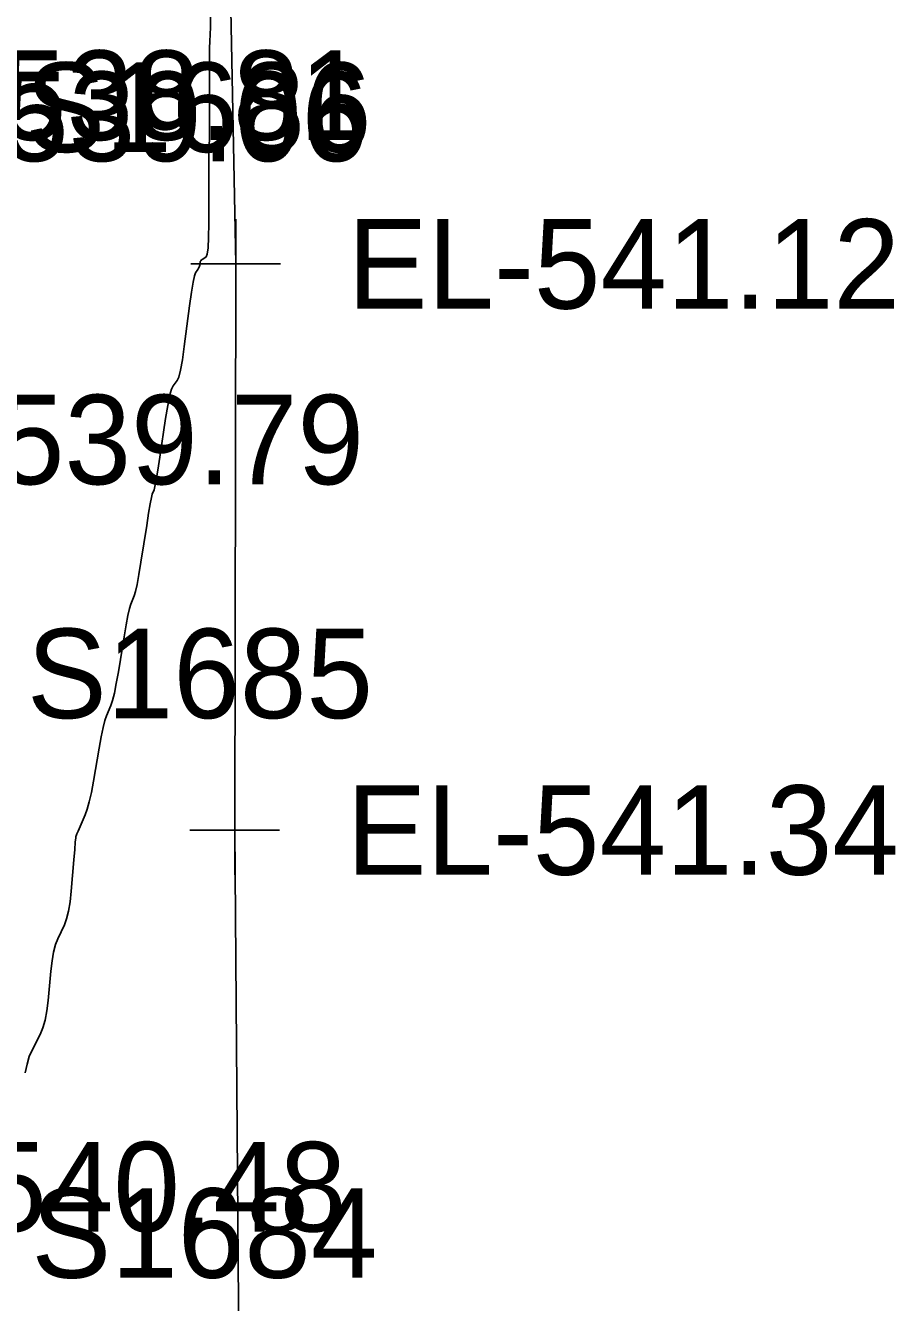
# Model space of a CAD drawing. Extents: x 1724534 to 1727318, y 657156 to 660047.
# Drawn here: x 1725539.2 to 1725578.1, y 658943.2 to 659000.3 of the extents above; entities that cross this region are included whole.
import ezdxf

# ---------------------------------------------------------------- set-up
doc = ezdxf.new("R2010")
doc.units = 0
for name, color, linetype in [('SURVEY - CONTOURS - Intermediate with optional Text', 7, 'Continuous'), ('SURVEY - DTM - Breaklines - Points - Elevations', 7, 'Continuous'), ('SURVEY - TRANSPORTATION - Features', 7, 'Continuous'), ('SURVEY - TRANSPORTATION - Features - Points - Elevations', 7, 'Continuous'), ('SURVEY - TRANSPORTATION - Features - Points - Locators', 7, 'Continuous'), ('SURVEY - TRANSPORTATION - Features - Points - Numbers', 7, 'Continuous')]:
    doc.layers.add(name, color=color, linetype=linetype)

msp = doc.modelspace()

# ---------------------------------------------------------------- linework, layer by layer
at = {"layer": 'SURVEY - CONTOURS - Intermediate with optional Text'}
msp.add_lwpolyline([(1725539.175, 658953.469), (1725539.254, 658953.853), (1725539.356, 658954.189), (1725539.48, 658954.478), (1725539.841, 658955.183), (1725539.965, 658955.477), (1725540.066, 658955.826), (1725540.145, 658956.233), (1725540.201, 658956.697), (1725540.319, 658958.009), (1725540.372, 658958.468), (1725540.441, 658958.863), (1725540.527, 658959.193), (1725540.629, 658959.458), (1725540.922, 658960.078), (1725541.024, 658960.346), (1725541.109, 658960.688), (1725541.178, 658961.102), (1725541.229, 658961.589), (1725541.345, 658962.984), (1725541.383, 658963.442), (1725541.411, 658963.769), (1725541.427, 658963.966), (1725541.433, 658964.036), (1725541.444, 658964.063), (1725541.478, 658964.14), (1725541.534, 658964.268), (1725541.854, 658964.993), (1725541.944, 658965.241), (1725542.036, 658965.576), (1725542.129, 658965.998), (1725542.223, 658966.507), (1725542.477, 658967.979), (1725542.568, 658968.484), (1725542.655, 658968.893), (1725542.735, 658969.207), (1725542.809, 658969.425), (1725543, 658969.88), (1725543.074, 658970.103), (1725543.155, 658970.429), (1725543.242, 658970.859), (1725543.334, 658971.393), (1725543.589, 658972.955), (1725543.68, 658973.485), (1725543.761, 658973.903), (1725543.832, 658974.21), (1725543.892, 658974.405), (1725544.041, 658974.777), (1725544.102, 658974.976), (1725544.173, 658975.294), (1725544.254, 658975.732), (1725544.344, 658976.289), (1725544.6, 658977.932), (1725544.688, 658978.481), (1725544.759, 658978.895), (1725544.813, 658979.175), (1725544.851, 658979.319), (1725544.93, 658979.526), (1725544.968, 658979.674), (1725545.023, 658979.966), (1725545.096, 658980.4), (1725545.185, 658980.977), (1725545.445, 658982.706), (1725545.54, 658983.284), (1725545.627, 658983.721), (1725545.707, 658984.017), (1725545.779, 658984.172), (1725545.964, 658984.398), (1725546.035, 658984.557), (1725546.112, 658984.866), (1725546.194, 658985.324), (1725546.281, 658985.931), (1725546.519, 658987.749), (1725546.602, 658988.353), (1725546.673, 658988.8), (1725546.731, 658989.09), (1725546.777, 658989.223), (1725546.882, 658989.37), (1725546.917, 658989.423), (1725546.944, 658989.473), (1725546.962, 658989.52), (1725546.971, 658989.564), (1725546.984, 658989.675), (1725546.995, 658989.717), (1725547.019, 658989.756), (1725547.056, 658989.795), (1725547.107, 658989.831), (1725547.257, 658989.927), (1725547.307, 658990.047), (1725547.343, 658990.335), (1725547.364, 658990.791), (1725547.372, 658991.415), (1725547.375, 658993.924), (1725547.378, 658994.374), (1725547.381, 658994.653), (1725547.385, 658994.761), (1725547.396, 658994.82), (1725547.4, 658994.928), (1725547.403, 658995.209), (1725547.405, 658995.663), (1725547.406, 658996.289), (1725547.407, 658998.189), (1725547.408, 658998.817), (1725547.411, 658999.274), (1725547.415, 658999.562), (1725547.421, 658999.681), (1725547.438, 658999.77), (1725547.444, 658999.888), (1725547.448, 659000.178), (1725547.45, 659000.638)], dxfattribs=at)
at = {"layer": 'SURVEY - TRANSPORTATION - Features'}
msp.add_lwpolyline([(1725552.257, 658864.379), (1725550.906, 658889.348), (1725550.236, 658914.341), (1725548.733, 658939.305), (1725548.535, 658964.315), (1725548.579, 658989.617), (1725548.091, 659014.622), (1725548.852, 659039.619), (1725549.567, 659064.874), (1725549.301, 659089.91), (1725550.369, 659114.889), (1725551.556, 659139.862), (1725552.642, 659165.042), (1725554.694, 659189.961), (1725556.721, 659214.883), (1725558.747, 659239.804), (1725561.49, 659264.678)], dxfattribs=at)
at = {"layer": 'SURVEY - TRANSPORTATION - Features - Points - Locators'}
for p, q in [((1725548.579, 658991.617), (1725548.579, 658987.617)), ((1725550.579, 658989.617), (1725546.579, 658989.617)), ((1725548.535, 658966.315), (1725548.535, 658962.315)), ((1725550.535, 658964.315), (1725546.535, 658964.315))]:
    msp.add_line(p, q, dxfattribs=at)

# ---------------------------------------------------------------- texts
at = {"layer": 'SURVEY - DTM - Breaklines - Points - Elevations'}
for s, p in [('EL-538.81', (1725529.72, 658995.154)), ('EL-538.81', (1725529.72, 658995.154)), ('EL-539.06', (1725529.814, 658994.206)), ('EL-539.79', (1725529.63, 658979.767)), ('EL-540.48', (1725528.837, 658946.374))]:
    msp.add_text(s, height=4, dxfattribs=at).set_placement(p)
at = {"layer": 'SURVEY - TRANSPORTATION - Features - Points - Elevations'}
for s, p in [('EL-541.12', (1725553.579, 658987.617)), ('EL-541.34', (1725553.535, 658962.315))]:
    msp.add_text(s, height=4, dxfattribs=at).set_placement(p)
at = {"layer": 'SURVEY - TRANSPORTATION - Features - Points - Numbers'}
for s, p in [('S1686', (1725539.181, 658994.617)), ('S1685', (1725539.247, 658969.315)), ('S1684', (1725539.445, 658944.305))]:
    msp.add_text(s, height=4, dxfattribs=at).set_placement(p)

doc.saveas('drawing.dxf')
